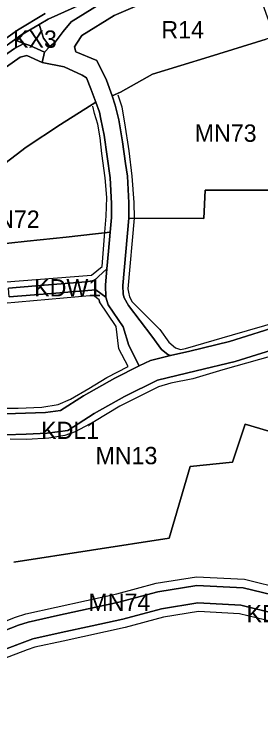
# Model space of a CAD drawing. Extents: x 7428841 to 7433518, y 5545054 to 5546840.
# Drawn here: x 7429914.7 to 7430056.9, y 5545838 to 5546245.5 of the extents above; entities that cross this region are included whole.
import ezdxf

# ---------------------------------------------------------------- set-up
doc = ezdxf.new("R2010")
doc.units = 0
for name, color, linetype in [('linie_rozgraniczajace', 7, 'Continuous'), ('linie_zabudowy_nieprzekraczalne', 7, 'Continuous'), ('oznaczenia_przeznaczen', 7, 'Continuous')]:
    doc.layers.add(name, color=color, linetype=linetype)

msp = doc.modelspace()

# ---------------------------------------------------------------- linework, layer by layer
at = {"layer": 'linie_rozgraniczajace'}
for points in [[(7429949.44, 5546226.76), (7429950.82, 5546228.81), (7429953.67, 5546233.22), (7429972.27, 5546244.79), (7429984.5, 5546249.98), (7430003.93, 5546257.84), (7430047.04, 5546271.67), (7430051.52, 5546269.16), (7430061.23, 5546241.83), (7430064.19, 5546232.61), (7430059.94, 5546231.03), (7430027.17, 5546220.98), (7429994.39, 5546210.92), (7429975.97, 5546200.5), (7429971.21, 5546198.5), (7429967.92, 5546207.41), (7429962.3, 5546218.77), (7429950.2, 5546223.83)], [(7429914.81, 5546230.77), (7429918.56, 5546233.43), (7429929.08, 5546239.65), (7429930.58, 5546234.76), (7429931.53, 5546231.66), (7429935.2, 5546226.96), (7429932.11, 5546223.61), (7429923.72, 5546227.43), (7429920.17, 5546228.57)], [(7429846.54, 5546100.39), (7429861.13, 5546119.63), (7429874.63, 5546131.35), (7429897.65, 5546150.58), (7429921.51, 5546168.74), (7429941.44, 5546181.94), (7429961.76, 5546194.72), (7429963.82, 5546189.06), (7429964.54, 5546184.93), (7429966.59, 5546175.7), (7429970.01, 5546151.12), (7429970.86, 5546136.41), (7429970.85, 5546128.34), (7429970.09, 5546119.91), (7429944.64, 5546116.84), (7429922.25, 5546114.62), (7429890.36, 5546111.21), (7429891.95, 5546067.04), (7429848.58, 5546063.8)], [(7429911.47, 5546087.59), (7429927.26, 5546088.81), (7429946.61, 5546090.36), (7429951.14, 5546090.8), (7429956.17, 5546091.27), (7429960.81, 5546091.85), (7429968.11, 5546098.66), (7429967.24, 5546089.28), (7429967.53, 5546082.3), (7429961.7, 5546086.64), (7429950.06, 5546085.67), (7429943.48, 5546085.05), (7429911.85, 5546082.6)]]:
    msp.add_lwpolyline(points, close=True, dxfattribs=at)
for points in [[(7429973.65, 5546260.5), (7429934.23, 5546242.7), (7429929.08, 5546239.65), (7429918.56, 5546233.43), (7429914.81, 5546230.77), (7429892.14, 5546214.67)], [(7429967.7, 5546253.72), (7429947.55, 5546241.18), (7429942.83, 5546235.46), (7429938.39, 5546229.35), (7429935.2, 5546226.96), (7429931.53, 5546231.66), (7429930.58, 5546234.76), (7429929.08, 5546239.65), (7429934.23, 5546242.7), (7429973.65, 5546260.5)], [(7429930.89, 5546217.68), (7429932.11, 5546223.61), (7429935.2, 5546226.96), (7429938.39, 5546229.35), (7429942.83, 5546235.46), (7429947.55, 5546241.18), (7429967.7, 5546253.72)], [(7429984.5, 5546249.98), (7429972.27, 5546244.79), (7429953.67, 5546233.22), (7429950.82, 5546228.81), (7429949.44, 5546226.76), (7429950.2, 5546223.83), (7429962.3, 5546218.77), (7429967.92, 5546207.41), (7429971.21, 5546198.5), (7429972.98, 5546193.04), (7429974.96, 5546184.57), (7429977.15, 5546171.98), (7429978.91, 5546159.36), (7429979.97, 5546152.13), (7429980.86, 5546136.69), (7429980.85, 5546127.87), (7429979.05, 5546108.44), (7429977.26, 5546089.02), (7429977.46, 5546084.05), (7429978.13, 5546081.97), (7429980.67, 5546077.45), (7429993.98, 5546059.75), (7429999.54, 5546052.14), (7430003.17, 5546049.3), (7430004.82, 5546048.78), (7429993.18, 5546045.73), (7429986.76, 5546042.68), (7429980.8, 5546054.43), (7429977.56, 5546065.15), (7429968.95, 5546077.84)], [(7429932.61, 5546245.81), (7429916.65, 5546236.37), (7429890.04, 5546217.47), (7429868.53, 5546200.53), (7429844.24, 5546182.48), (7429819.06, 5546159.11), (7429803.55, 5546141.79), (7429775.47, 5546107.09), (7429727.84, 5546041.79), (7429712.38, 5546019.62), (7429694.69, 5545991.97), (7429678.9, 5545965.27), (7429661.41, 5545937.52), (7429642.2, 5545909.04), (7429627.76, 5545889.55), (7429578.46, 5545830.77), (7429550.53, 5545801.9), (7429533.05, 5545787.63), (7429518.17, 5545776.56), (7429482.58, 5545755.61)], [(7429482.58, 5545755.61), (7429518.17, 5545776.56), (7429533.05, 5545787.63), (7429550.53, 5545801.9), (7429578.46, 5545830.77), (7429627.76, 5545889.55), (7429642.2, 5545909.04), (7429661.41, 5545937.52), (7429678.9, 5545965.27), (7429694.69, 5545991.97), (7429712.38, 5546019.62), (7429727.84, 5546041.79), (7429775.47, 5546107.09), (7429803.55, 5546141.79), (7429819.06, 5546159.11), (7429844.24, 5546182.48), (7429868.53, 5546200.53), (7429890.04, 5546217.47), (7429916.65, 5546236.37), (7429932.61, 5546245.81)], [(7429892.14, 5546214.67), (7429914.81, 5546230.77), (7429920.17, 5546228.57), (7429914.96, 5546225.81), (7429890.23, 5546208.55)], [(7429890.23, 5546208.55), (7429914.96, 5546225.81), (7429920.17, 5546228.57), (7429923.72, 5546227.43), (7429932.11, 5546223.61), (7429930.89, 5546217.68), (7429921.89, 5546221.67), (7429918.09, 5546220.68), (7429893.78, 5546203.71)], [(7430072.78, 5546144.05), (7430024.7, 5546144.06), (7430023.94, 5546127.72), (7429980.85, 5546127.87), (7429980.86, 5546136.69), (7429979.97, 5546152.13), (7429978.91, 5546159.36), (7429977.15, 5546171.98), (7429974.96, 5546184.57), (7429972.98, 5546193.04), (7429971.21, 5546198.5), (7429975.97, 5546200.5), (7429994.39, 5546210.92), (7430027.17, 5546220.98), (7430059.94, 5546231.03)], [(7429893.78, 5546203.71), (7429918.09, 5546220.68), (7429921.89, 5546221.67), (7429930.89, 5546217.68), (7429943.46, 5546215.22), (7429953.78, 5546210.42), (7429956.42, 5546208.72), (7429958.95, 5546202.39), (7429961.76, 5546194.72), (7429941.44, 5546181.94), (7429921.51, 5546168.74), (7429897.65, 5546150.58)], [(7429968.95, 5546077.84), (7429967.53, 5546082.3), (7429967.24, 5546089.28), (7429968.11, 5546098.66), (7429969.04, 5546108.81), (7429970.09, 5546119.91), (7429970.85, 5546128.34), (7429970.86, 5546136.41), (7429970.01, 5546151.12), (7429966.59, 5546175.7), (7429964.54, 5546184.93), (7429963.82, 5546189.06), (7429961.76, 5546194.72), (7429958.95, 5546202.39), (7429956.42, 5546208.72), (7429953.78, 5546210.42), (7429943.46, 5546215.22), (7429930.89, 5546217.68)], [(7430069.41, 5546066.31), (7430038.84, 5546056.81), (7430016.01, 5546051.27), (7430004.82, 5546048.78), (7430003.17, 5546049.3), (7429999.54, 5546052.14), (7429993.98, 5546059.75), (7429980.67, 5546077.45), (7429978.13, 5546081.97), (7429977.46, 5546084.05), (7429977.26, 5546089.02), (7429979.05, 5546108.44), (7429980.85, 5546127.87), (7430023.94, 5546127.72), (7430024.7, 5546144.06), (7430072.78, 5546144.05)], [(7429890.36, 5546111.21), (7429922.25, 5546114.62), (7429944.64, 5546116.84), (7429970.09, 5546119.91), (7429969.04, 5546108.81), (7429968.11, 5546098.66), (7429960.81, 5546091.85), (7429956.17, 5546091.27), (7429951.14, 5546090.8), (7429946.61, 5546090.36), (7429927.26, 5546088.81), (7429911.47, 5546087.59)], [(7429911.85, 5546082.6), (7429943.48, 5546085.05), (7429950.06, 5546085.67), (7429961.7, 5546086.64), (7429967.53, 5546082.3), (7429968.95, 5546077.84), (7429977.56, 5546065.15), (7429980.8, 5546054.43), (7429986.76, 5546042.68), (7429972.76, 5546035.67), (7429954.62, 5546025.5), (7429941.42, 5546017.03), (7429932.7, 5546015.79), (7429921.21, 5546015.41), (7429909.72, 5546015.03)], [(7429909.72, 5546015.03), (7429921.21, 5546015.41), (7429932.7, 5546015.79), (7429941.42, 5546017.03), (7429954.62, 5546025.5), (7429972.76, 5546035.67), (7429986.76, 5546042.68), (7429993.18, 5546045.73), (7430004.82, 5546048.78), (7430016.01, 5546051.27), (7430038.84, 5546056.81), (7430069.41, 5546066.31), (7430098.81, 5546071.19), (7430108.97, 5546073.51)], [(7429909.57, 5546003.02), (7429921.65, 5546003.42), (7429933.74, 5546003.82), (7429945.7, 5546005.52), (7429960.8, 5546015.2), (7429978.35, 5546025.05), (7429997.3, 5546034.38), (7430019.67, 5546039.81), (7430042.04, 5546045.23), (7430072.19, 5546054.6)], [(7430072.19, 5546054.6), (7430042.04, 5546045.23), (7430019.67, 5546039.81), (7429997.3, 5546034.38), (7429978.35, 5546025.05), (7429960.8, 5546015.2), (7429945.7, 5546005.52), (7429933.74, 5546003.82), (7429921.65, 5546003.42), (7429909.57, 5546003.02)], [(7430080.36, 5545999.48), (7430047.86, 5546009.17), (7430040.62, 5545987.1), (7430016.06, 5545984.65), (7430003.99, 5545943.38), (7429914.54, 5545929.5)], [(7429914.54, 5545929.5), (7430003.99, 5545943.38), (7430016.06, 5545984.65), (7430040.62, 5545987.1), (7430047.86, 5546009.17), (7430080.36, 5545999.48)], [(7429902.74, 5545887.57), (7429917.2, 5545893.14), (7429922.72, 5545894.95), (7429939.71, 5545898.68), (7429975.03, 5545906.41), (7429997.54, 5545912.46), (7430020.02, 5545916.06), (7430046.71, 5545914.73), (7430068.96, 5545909.28)], [(7430068.96, 5545909.28), (7430046.71, 5545914.73), (7430020.02, 5545916.06), (7429997.54, 5545912.46), (7429975.03, 5545906.41), (7429939.71, 5545898.68), (7429922.72, 5545894.95), (7429917.2, 5545893.14), (7429902.74, 5545887.57)], [(7430185.25, 5545837.88), (7430169.33, 5545846.21), (7430153.41, 5545854.54), (7430142.65, 5545861.18), (7430135.68, 5545864.5), (7430123.93, 5545871.01), (7430112.18, 5545877.53), (7430096.87, 5545884.81), (7430065.56, 5545899.82), (7430045.26, 5545904.79), (7430020.57, 5545906.02), (7429999.63, 5545902.67), (7429977.4, 5545896.7), (7429959.62, 5545892.8), (7429941.85, 5545888.91), (7429925.35, 5545885.29), (7429905.91, 5545878.08)], [(7429905.91, 5545878.08), (7429925.35, 5545885.29), (7429941.85, 5545888.91), (7429959.62, 5545892.8), (7429977.4, 5545896.7), (7429999.63, 5545902.67), (7430020.57, 5545906.02), (7430045.26, 5545904.79), (7430065.56, 5545899.82), (7430096.87, 5545884.81), (7430112.18, 5545877.53), (7430123.93, 5545871.01), (7430135.68, 5545864.5), (7430142.65, 5545861.18), (7430153.41, 5545854.54), (7430169.33, 5545846.21), (7430185.25, 5545837.88)]]:
    msp.add_lwpolyline(points, dxfattribs=at)
at = {"layer": 'linie_zabudowy_nieprzekraczalne'}
for points in [[(7429974.39, 5546199.08), (7429976.68, 5546192.17), (7429977.67, 5546186.1)], [(7429962.93, 5546182.18), (7429961.05, 5546188.25), (7429959.95, 5546192.43)], [(7429977.67, 5546186.1), (7429978.31, 5546182.87), (7429980.69, 5546166.79), (7429982.45, 5546152.18), (7429983.67, 5546136.91), (7429983.84, 5546127.84), (7429980.27, 5546087.18), (7429980.62, 5546085.19), (7429981.24, 5546082.49), (7429982.75, 5546079.73), (7429998.56, 5546063.65), (7430003.89, 5546056.35), (7430007.67, 5546053.2)], [(7429965.49, 5546100.05), (7429966.67, 5546117.45), (7429967.8, 5546129.05), (7429968.05, 5546139.84), (7429967.21, 5546151.05), (7429965.17, 5546165.15), (7429964.2, 5546174.29), (7429962.93, 5546182.18)], [(7429963.7, 5546080.81), (7429960.45, 5546083.27), (7429908.57, 5546078.73), (7429907.69, 5546091.05), (7429959.24, 5546095.05), (7429965.49, 5546100.05)], [(7430007.67, 5546053.2), (7430010.48, 5546052.1), (7430013.34, 5546052.73), (7430040.62, 5546060.65), (7430067.9, 5546068.57), (7430074.2, 5546070.07), (7430086.27, 5546071.65), (7430100.47, 5546074.17), (7430110.9, 5546077.25), (7430130.07, 5546087.79), (7430145.09, 5546094.11)], [(7429980.3, 5546042.36), (7429975.02, 5546052.54), (7429973.5, 5546065.38), (7429963.86, 5546079.59), (7429963.66, 5546080.82), (7429963.86, 5546079.59)], [(7430077.46, 5546052.35), (7430056.13, 5546046.46), (7430034.96, 5546040.46), (7430017.64, 5546035.24), (7430005.07, 5546032.71), (7429997.78, 5546030.68), (7429975.58, 5546019.53), (7429961.03, 5546010.66), (7429949.93, 5546004.74), (7429943.89, 5546002.66), (7429934.74, 5546001), (7429921.82, 5546000.3), (7429912.29, 5546000.5)], [(7429749.93, 5546005.61), (7429765.5, 5546009), (7429780.94, 5546011.51), (7429801.93, 5546015.2), (7429818.17, 5546017.53), (7429834.41, 5546019.85), (7429844.59, 5546020.77), (7429857.23, 5546021.19), (7429877.88, 5546020.42), (7429902.96, 5546018.42), (7429917.04, 5546018.26), (7429930.64, 5546018.81), (7429940.01, 5546020.35), (7429947.23, 5546023.49), (7429957.72, 5546029.59), (7429968.03, 5546035.92), (7429980.3, 5546042.36)], [(7429901.15, 5545892.32), (7429915.52, 5545897.85), (7429921.4, 5545899.78), (7429956.3, 5545907.43), (7429973.84, 5545911.27), (7429996.49, 5545917.36), (7430019.74, 5545921.08), (7430047.43, 5545919.7), (7430070.66, 5545914.01), (7430088.05, 5545905.62), (7430119.05, 5545890.87), (7430142.55, 5545877.84), (7430149.84, 5545874.37), (7430160.84, 5545867.58), (7430191.7, 5545851.43), (7430204.69, 5545845.83), (7430216.27, 5545843.99), (7430271.14, 5545845.08), (7430286.27, 5545846.68)], [(7430194.95, 5545828.25), (7430183.1, 5545833.36), (7430150.94, 5545850.19), (7430140.26, 5545856.78), (7430133.39, 5545860.05), (7430109.89, 5545873.08), (7430094.72, 5545880.3), (7430063.87, 5545895.09), (7430044.53, 5545899.82), (7430020.84, 5545901), (7430000.68, 5545897.77), (7429978.58, 5545891.84), (7429942.92, 5545884.02), (7429926.67, 5545880.46), (7429922.24, 5545879.01), (7429907.5, 5545873.33)]]:
    msp.add_lwpolyline(points, dxfattribs=at)

# ---------------------------------------------------------------- texts
at = {"layer": 'oznaczenia_przeznaczen'}
for s, p in [('R14', (7429999.54, 5546231.54)), ('KX3', (7429914.01, 5546226.12)), ('MN73', (7430018.74, 5546171.92)), ('MN72', (7429893.7, 5546122.31)), ('KDW1', (7429926.2, 5546082.73)), ('KDL1', (7429930.21, 5546000.52)), ('MN13', (7429961.57, 5545985.99)), ('MN74', (7429957.47, 5545901.41)), ('KDD3', (7430048.6, 5545894.82))]:
    msp.add_text(s, height=10, dxfattribs=at).set_placement(p)

doc.saveas('drawing.dxf')
